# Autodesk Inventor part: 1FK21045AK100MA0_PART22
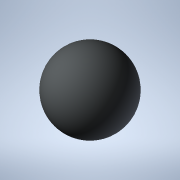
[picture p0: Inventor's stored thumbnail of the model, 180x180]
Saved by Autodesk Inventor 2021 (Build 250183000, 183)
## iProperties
Created: 2025-04
Part Number: 1FK21045AK100MA0_PART22
Material: Generic
Catalog Web Link: www.3dfindit.com
Description: -Servo synchronous motor
Document SubType Name: Modeling
Designer: psAdmin
Mass: 0.137258 g
Surface Area: 1.2868 cm^2
Volume: 0.137258 cm^3
Density: 1 g/cm^3
Appearance: PSOLRGB-212-217-219
Category: PARTsolutions
Title: 1FK21045AK100MA0_PART22
Author: Cadenas PARTsolutions
Comments: Servo synchronous motor
Sending System: PARTsolutions
Preprocessor: ST-DEVELOPER v19.3
PSOL_IDENT_0: {$CADENAS_DATA/23d-libs/siemens_ag/_cat_/e0/5f/1fk21045ak100ma0.prj},216 {VTYP=3D},{NB=1FK21045AK100
PSOL_IDENT_1: MA0_PART22},{LINA=1FK21045AK100MA0_PART22},{NN=1FK21045AK100MA0_PART22},{NOPRJ=TRUE},{DATE=19.08.202
PSOL_IDENT_2: 5 14:01:03},{GEOMDATE=30.07.2025 02:01:57},{VERSION=},{LINEID=10},{WBVAR=},{WBNUMERIC=}  {NB=1FK2104
PSOL_IDENT_3: 5AK100MA0_PART22},{LINA=1FK21045AK100MA0_PART22},{KT=DUMMY},{PREVIEW=../../../_pool_/0f/2c/p_d211_xx
PSOL_IDENT_4: _00438j.png},{DESCSHORT=SIMOTICS S-1FK2 HD, SINAMICS S210 3AC 400V-480V, 1.7 Nm, 6000 rpm},{DESCLONG=
PSOL_IDENT_5: SIMOTICS S-1FK2 HD servo motor M0=2.4 Nm; PN = 1.07 kW at nN=6000 rpm (380-480 V); PN = 0.75 kW at n
PSOL_IDENT_6: N=3000 rpm (200-240 V); with holding brake; degree of protection IP64; cylindrical shaft D19x40mm; a
PSOL_IDENT_7: bsolute encoder 22-bit + 12-bit multiturn (encoder AM22DQC); with OCC interface; plug size M17, rota
PSOL_IDENT_8: table; SIMOTICS S-1FK2 servomotorfor a wide range of uses in industrial environments. SIMOTICS S‑1FK
PSOL_IDENT_9: 2 servomotors are compact synchronous motors with a high dynamic performance that set themselves apa
PSOL_IDENT_10: rt as a result of their high power density, degree of protection and overload capability. The motors
PSOL_IDENT_11: are available in two variants: as High Dynamic variant (highest dynamic performance as a result of
PSOL_IDENT_12: the low intrinsic moment of inertia for applications demanding a high dynamic performance with low m
PSOL_IDENT_13: oved masses) - and as Compact variant (precise and stable closed-loop control for medium up to large
PSOL_IDENT_14: moved masses as a result of a medium intrinsic moment of inertia). SIMOTICSS‑1FK2 servomotors fully
PSOL_IDENT_15: exploit their strengths in a system with the SINAMICSS210 frequency converter and simple connection
PSOL_IDENT_16: using the one cable connection (OCC). Advantages include the short control and positioning times, f
PSOL_IDENT_17: ast and precise correction of disturbing quantities as well as stable control with a high dynamic pe
PSOL_IDENT_18: rformance. The servo motors can be configured to address a wide range of requirements. For example w
PSOL_IDENT_19: ith and without holding brake, IP64 or IP65 degree of protection, singleturn or multiturn absolute e
PSOL_IDENT_20: ncoders - to name just a few. Further, the servomotors are available in different shaft heights exte
PSOL_IDENT_21: nding from 20 to 100. A shaft sealing ring is available to achieve an IP65 degree of protection and
PSOL_IDENT_22: for subsequent mounting at the motor or as spare part. SIMOTICS - the optimum motor for each and eve
PSOL_IDENT_23: ry motion control application.},{INTNO=804766807114},{SUPPLIERALTNO=1FK2104-5AK10-0MA0},{MANUID=1FK2
PSOL_IDENT_24: 1045AK100MA0},{MANUNAME=Siemens},{MANUTYPEDESC=Synchronous motor 1FK2-HD 2,39 Nm},{AAU732=SIMOTICS},
PSOL_IDENT_25: {AAO057=S-1FK2},{AAU734=SIMOTICS S-1FK2 HD servo motor M0=2.4 Nm; PN = 1.07 kW at nN=6000 rpm (380-4
PSOL_IDENT_26: 80 V); PN = 0.75 kW at nN=3000 rpm (200-240 V); with holding brake; degree of protection IP64; cylin
PSOL_IDENT_27: drical shaft D19x40mm; absolute encoder 22-bit + 12-bit multiturn (encoder AM22DQC); with OCC interf
PSOL_IDENT_28: ace; plug size M17, rotatable;},{AAW338=Synchronous motor 1FK2-HD 2,39 Nm},{AAO742=SIMOTICS},{AAO663=
PSOL_IDENT_29: 4042948691236},{NOCUPEROU=1},{PRICEQUANTITY=1},{QUANTITYMIN=1},{QUANTITYINT=1},{CTN=85015100},{COO=D
PSOL_IDENT_30: E},{AAO676=1FK2104-5AK10-0MA0},{AAO677=Siemens AG},{ORDERUNIT=C62},{CONTENTUNIT=C62}
NB: 1FK21045AK100MA0_PART22
NT: Servo synchronous motor
NBSYN: $MANUID._PART22
LINA: 1FK21045AK100MA0_PART22
CATALOG: SIEMENS
PREVIEW: ../../../_pool_/0f/2c/p_d211_xx_00438j.png
DESCSHORT: SIMOTICS S-1FK2 HD, SINAMICS S210 3AC 400V-480V, 1.7 Nm, 6000 rpm
DESCLONG: SIMOTICS S-1FK2 HD servo motor M0=2.4 Nm; PN = 1.07 kW at nN=6000 rpm (380-480 V); PN = 0.75 kW at nN=3000 rpm (200-240 V); with holding brake; degree of protec
INTNO: 804766807114
SUPPLIERALTNO: 1FK2104-5AK10-0MA0
MANUID: 1FK21045AK100MA0
MANUNAME: Siemens
MANUTYPEDESC: Synchronous motor 1FK2-HD 2,39 Nm
AAU732: SIMOTICS
AAO057: S-1FK2
AAU734: SIMOTICS S-1FK2 HD servo motor M0=2.4 Nm; PN = 1.07 kW at nN=6000 rpm (380-480 V); PN = 0.75 kW at nN=3000 rpm (200-240 V); with holding brake; degree of protec
AAW338: Synchronous motor 1FK2-HD 2,39 Nm
AAO742: SIMOTICS
AAO663: 4042948691236.0
NOCUPEROU: 1
PRICEQUANTITY: 1
QUANTITYMIN: 1
QUANTITYINT: 1
CTN: 85015100
COO: DE
ARTICLENO: 1FK21045AK100MA0_PART22
BOMINFO: 1FK21045AK100MA0_PART22
CREATOR: CADENAS GmbH
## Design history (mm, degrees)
feature "2025_04_17_15_45_15_0090"
body "Solid1"
